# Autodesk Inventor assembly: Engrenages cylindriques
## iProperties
Created: 2011-07
Part Number: Engrenages cylindriques
Document SubType Name: Assembly
Designer: Laur
ClientObjectVersion: 1
Author: Laur
